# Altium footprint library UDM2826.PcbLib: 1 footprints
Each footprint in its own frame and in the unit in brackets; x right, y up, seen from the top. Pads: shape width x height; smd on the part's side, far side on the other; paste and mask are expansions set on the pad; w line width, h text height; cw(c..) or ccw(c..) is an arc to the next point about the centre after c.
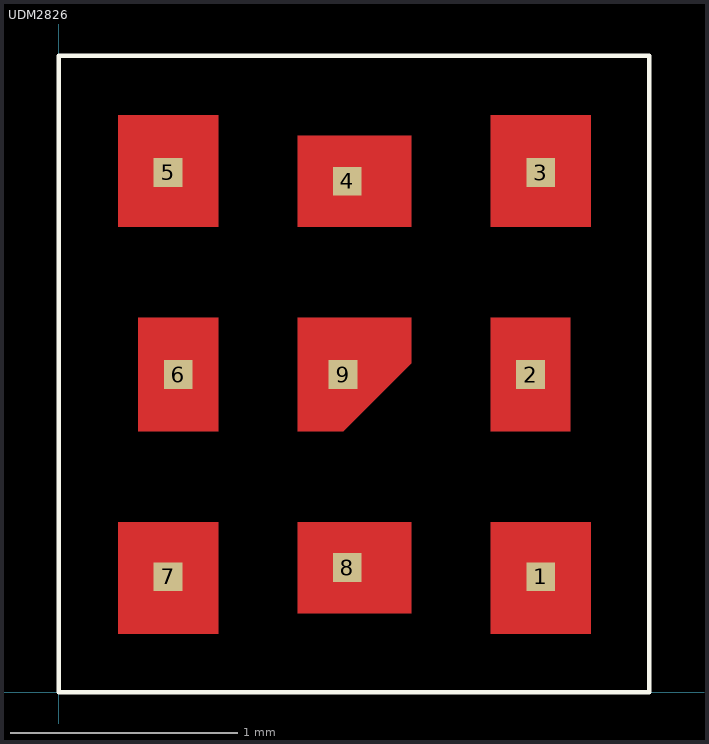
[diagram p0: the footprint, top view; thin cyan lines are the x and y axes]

## UDM2826 [mil]
pads (9):
  rect 5x5 smd mask+0: 1(83.53,20) 2(81.76,55) 3(83.53,90) 4(50,88.5) 5(18.96,90) 6(20.73,55) 7(18.96,20) 8(50,21.57) 9(49.28,55)
Top Layer:
  region: 10.3,80.62 27.62,80.62 27.62,99.92 10.3,99.92
  region: 41.4,80.62 61.09,80.62 61.09,96.37 41.4,96.37
  region: 74.87,80.62 92.19,80.62 92.19,99.92 74.87,99.92
  region: 74.87,45.19 74.87,64.88 88.65,64.88 88.65,45.19
  region: 41.4,45.19 41.4,64.88 61.09,64.88 61.09,57 49.28,45.19
  region: 13.84,45.19 13.84,64.88 27.62,64.88 27.62,45.19
  region: 10.3,10.15 27.62,10.15 27.62,29.44 10.3,29.44
  region: 41.4,13.69 41.4,29.44 61.09,29.44 61.09,13.69
  region: 74.87,10.15 92.19,10.15 92.19,29.44 74.87,29.44
Top Overlay:
  lines w0.79: 0,0 0,110.24 102.36,110.24 102.36,0 0,0
Top Paste:
  region: 10.3,80.62 27.62,80.62 27.62,99.92 10.3,99.92
  region: 41.4,80.62 61.09,80.62 61.09,96.37 41.4,96.37
  region: 74.87,80.62 92.19,80.62 92.19,99.92 74.87,99.92
  region: 74.87,45.19 74.87,64.88 88.65,64.88 88.65,45.19
  region: 41.4,45.19 41.4,64.88 61.09,64.88 61.09,57 49.28,45.19
  region: 13.84,45.19 13.84,64.88 27.62,64.88 27.62,45.19
  region: 10.3,10.15 27.62,10.15 27.62,29.44 10.3,29.44
  region: 41.4,13.69 41.4,29.44 61.09,29.44 61.09,13.69
  region: 74.87,10.15 92.19,10.15 92.19,29.44 74.87,29.44
Top Solder:
  region: 10.3,80.62 27.62,80.62 27.62,99.92 10.3,99.92
  region: 41.4,80.62 61.09,80.62 61.09,96.37 41.4,96.37
  region: 74.87,80.62 92.19,80.62 92.19,99.92 74.87,99.92
  region: 74.87,45.19 74.87,64.88 88.65,64.88 88.65,45.19
  region: 41.4,45.19 41.4,64.88 61.09,64.88 61.09,57 49.28,45.19
  region: 13.84,45.19 13.84,64.88 27.62,64.88 27.62,45.19
  region: 10.3,10.15 27.62,10.15 27.62,29.44 10.3,29.44
  region: 41.4,13.69 41.4,29.44 61.09,29.44 61.09,13.69
  region: 74.87,10.15 92.19,10.15 92.19,29.44 74.87,29.44
3D body: height 0.39, standoff -47.44, extent 0,0 0,0
3D body: height 47.68, standoff 0, extent -0.01,0.02 102.36,110.25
